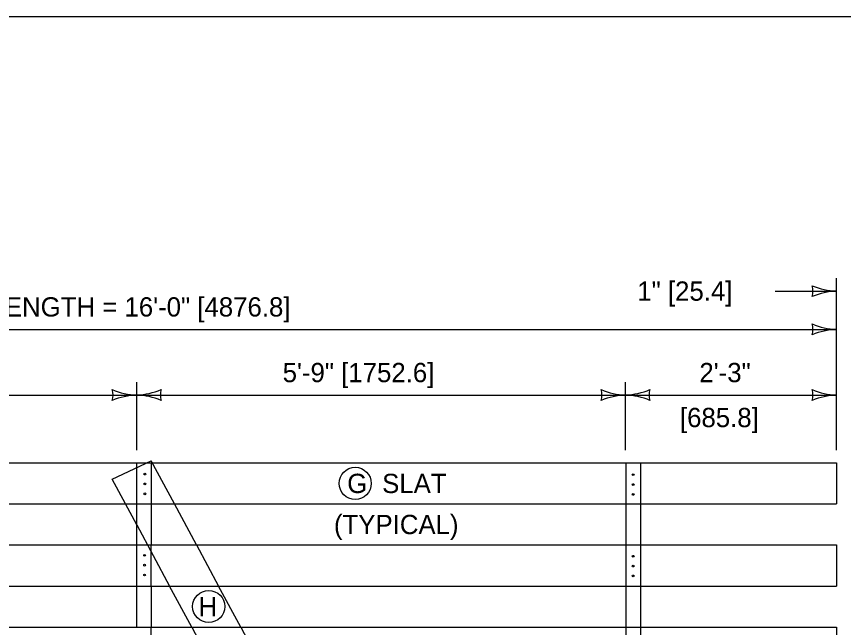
# Model space of a CAD drawing. Extents: x 49991.4 to 50021, y 49987.6 to 50011.4.
# Drawn here: x 50002.489 to 50005.062, y 49997.098 to 49998.999 of the extents above; entities that cross this region are included whole.
import ezdxf

# ---------------------------------------------------------------- set-up
doc = ezdxf.new("R2010")
doc.units = 0
for name, color, linetype in [('Level 1', 7, 'Continuous'), ('Level 2', 7, 'Continuous'), ('Level 3', 7, 'Continuous'), ('Level 4', 7, 'Continuous')]:
    doc.layers.add(name, color=color, linetype=linetype)

msp = doc.modelspace()

# ---------------------------------------------------------------- linework, layer by layer
at = {"layer": 'Level 1'}
for p, q in [((50000.6929, 49997.6101), (50005.041, 49997.6101)), ((50005.041, 49997.6101), (50005.041, 49997.4824)), ((50001.1893, 49997.4824), (50005.041, 49997.4824)), ((50002.8632, 49997.4174), (50002.8282, 49997.4824)), ((50002.8632, 49997.3546), (50002.8632, 49997.4824)), ((50002.9084, 49997.4824), (50002.9084, 49997.3546)), ((50003.0492, 49997.3546), (50002.9806, 49997.4824)), ((50004.386, 49997.3546), (50004.386, 49997.4824)), ((50004.4313, 49997.4824), (50004.4313, 49997.3546)), ((50001.3604, 49997.3546), (50005.041, 49997.3546)), ((50005.041, 49997.3546), (50005.041, 49997.2268)), ((50001.5315, 49997.2268), (50005.041, 49997.2268)), ((50002.8632, 49997.099), (50002.8632, 49997.2268)), ((50002.9084, 49997.2268), (50002.9084, 49997.099)), ((50003.0346, 49997.099), (50002.9656, 49997.2268)), ((50003.1868, 49997.099), (50003.118, 49997.2268)), ((50004.386, 49997.099), (50004.386, 49997.2268)), ((50004.4313, 49997.2268), (50004.4313, 49997.099)), ((50001.7026, 49997.099), (50005.041, 49997.099)), ((50005.041, 49997.099), (50005.041, 49996.9713))]:
    msp.add_line(p, q, dxfattribs=at)
msp.add_lwpolyline([(49999.3835, 49998.9992), (50016.7501, 49998.9992), (50016.7501, 49987.7988), (49999.3835, 49987.7988)], close=True, dxfattribs=at)
for centre in [(50002.8887, 49997.5752), (50004.4078, 49997.5733), (50002.8887, 49997.5446), (50004.4078, 49997.5427), (50002.8887, 49997.5139), (50004.4078, 49997.512), (50002.8877, 49997.3225), (50004.4078, 49997.3197), (50002.8877, 49997.2919), (50004.4078, 49997.289), (50002.8877, 49997.2612), (50004.4078, 49997.2584)]:
    msp.add_ellipse(centre, major_axis=(0.00285, 0), ratio=0.940299, dxfattribs=at)
at = {"layer": 'Level 2'}
for centre in [(50003.5431, 49997.5463), (50003.0871, 49997.1631)]:
    msp.add_circle(centre, 0.05, dxfattribs=at)
at = {"layer": 'Level 3'}
for p, q in [((50005.041, 49997.6501), (50005.041, 49998.1848)), ((50004.8494, 49998.1448), (50005.041, 49998.1448)), ((50000.6929, 49998.0256), (50005.041, 49998.0256)), ((50002.8632, 49997.6501), (50002.8632, 49997.8613)), ((50004.3842, 49997.6501), (50004.3842, 49997.8613)), ((50001.3006, 49997.8213), (50002.8632, 49997.8213)), ((50002.8632, 49997.8213), (50004.3842, 49997.8213)), ((50004.3842, 49997.8213), (50005.041, 49997.8213))]:
    msp.add_line(p, q, dxfattribs=at)
for centre, radius, start, end in [((50005.0502, 49998.3669), 0.2223, 247.456, 267.6395), ((50004.9128, 49998.1448), 0.0548, 342.1388, 17.8612), ((50005.0525, 49997.9121), 0.233, 92.8273, 112.0772), ((50005.0502, 49998.2477), 0.2223, 247.456, 267.6395), ((50004.9128, 49998.0256), 0.0548, 342.1388, 17.8612), ((50005.0525, 49997.7929), 0.233, 92.8273, 112.0772), ((50002.8724, 49998.0434), 0.2223, 247.456, 267.6395), ((50002.735, 49997.8213), 0.0548, 342.1388, 17.8612), ((50002.8517, 49998.054), 0.233, 272.8273, 292.0772), ((50002.9914, 49997.8213), 0.0548, 162.1388, 197.8612), ((50004.3934, 49998.0434), 0.2223, 247.456, 267.6395), ((50004.256, 49997.8213), 0.0548, 342.1388, 17.8612), ((50004.3727, 49998.054), 0.233, 272.8273, 292.0772), ((50004.5124, 49997.8213), 0.0548, 162.1388, 197.8612), ((50005.0502, 49998.0434), 0.2223, 247.456, 267.6395), ((50004.9128, 49997.8213), 0.0548, 342.1388, 17.8612), ((50002.8747, 49997.5886), 0.233, 92.8273, 112.0772), ((50002.854, 49997.5992), 0.2223, 67.456, 87.6395), ((50004.3957, 49997.5886), 0.233, 92.8273, 112.0772), ((50004.375, 49997.5992), 0.2223, 67.456, 87.6395), ((50005.0525, 49997.5886), 0.233, 92.8273, 112.0772)]:
    msp.add_arc(centre, radius, start, end, dxfattribs=at)
at = {"layer": 'Level 4'}
for p, q in [((50002.787, 49997.559), (50002.9083, 49997.6168)), ((50002.8632, 49997.4824), (50002.8632, 49997.6101)), ((50002.9806, 49997.4824), (50002.9083, 49997.6168)), ((50002.9084, 49997.6101), (50002.9084, 49997.4824)), ((50004.386, 49997.4824), (50004.386, 49997.6101)), ((50004.4313, 49997.6101), (50004.4313, 49997.4824)), ((50002.8282, 49997.4824), (50002.787, 49997.559)), ((50002.8632, 49997.4174), (50002.9656, 49997.2268)), ((50002.8632, 49997.2268), (50002.8632, 49997.3546)), ((50002.9084, 49997.2268), (50002.9084, 49997.3546)), ((50003.0492, 49997.3546), (50003.118, 49997.2268)), ((50004.386, 49997.2268), (50004.386, 49997.3546)), ((50004.4313, 49997.3546), (50004.4313, 49997.2268)), ((50002.9084, 49996.9713), (50002.9084, 49997.099)), ((50003.0346, 49997.099), (50003.1038, 49996.97)), ((50003.1868, 49997.099), (50003.2562, 49996.97)), ((50004.386, 49996.97), (50004.386, 49997.099)), ((50004.4313, 49997.099), (50004.4313, 49996.97))]:
    msp.add_line(p, q, dxfattribs=at)

# ---------------------------------------------------------------- texts
at = {"layer": 'Level 2'}
for s, p in [('1" [25.4]', (50004.4208, 49998.1148)), ('PANEL LENGTH = 16\'-0" [4876.8]', (50002.1227, 49998.0656)), ('5\'-9" [1752.6]', (50003.3173, 49997.8613)), ('2\'-3"', (50004.6141, 49997.8613)), ('[685.8]', (50004.5536, 49997.7213)), ('G', (50003.5182, 49997.5163)), ('SLAT', (50003.6268, 49997.5162)), ('(TYPICAL) ', (50003.4768, 49997.3884)), ('H', (50003.0551, 49997.1331))]:
    msp.add_text(s, height=0.06, dxfattribs=at).set_placement(p)

doc.saveas('drawing.dxf')
